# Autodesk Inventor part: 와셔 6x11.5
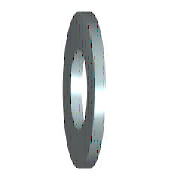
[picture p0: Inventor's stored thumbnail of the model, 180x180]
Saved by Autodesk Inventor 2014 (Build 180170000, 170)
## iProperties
IsCustomPart: 1
Created: 2012-02
Part Number: 와셔 6x11.5
Material: 강철, 연강
Description: 평면 와셔
Document SubType Name: Modeling
Standard: KS B 1326
Designer: mduedu
Standards Organization: KS
Language: ko-KR
Size Designation: 6x11.5
Categories: <MemberInstance><Categories><Category DisplayName="조임쇠" InternalName="e4da775c-781d-43d5-af7c-5136215cf5a6" Mnemonic="FSTN"><Category DisplayName="와셔" InternalN
Density: 1 g/cm^3
Appearance: Orange
Author: mduedu
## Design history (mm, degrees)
sketch "스케치"
  geometry: C1 r 5.75 at (0, 0); C2 r 3.2 at (0, 0); 1 further point
  constraints: 2 centre point, 2 coincident
  dimensions: "d0" = 6.4 diameter of C2 (= SD1); "d1" = 11.5 diameter of C1 (= SD2)
extrude "본체" new body sketch "스케치" distance "d2" = 1.6 (= SD); taper "d3" = 0 deg
workaxis "Work Axis1"
workplane "Work Plane1"
body "Solid1"
other parameters: "SD1" = 6.4 [user parameter; used in 1 equation term], "SD2" = 11.5 [user parameter; used in 1 equation term], "SD" = 1.6 [user parameter; used in 1 equation term], "d4" = 0, "d5" = 0, "d6" = 0, "d7" = 0, "NND" = 6 [user parameter]
